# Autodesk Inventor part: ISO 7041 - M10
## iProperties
Comments: To add or edit properties for Autodesk Inventor files, use iProperties.
Created: 2004-03
Part Number: ISO 7041 - M10
Vendor: Autodesk Inc.
Document SubType Name: Modeling
Designer: rak
Material: Default
Description: Hex Nut with Torque Part
Standard: ISO 7041
Size Designation: M10
Alert: To add or edit properties for Autodesk Inventor files, use iProperties.
Control State: 0
Master: False
Checked Out: False
Shininess: 64.0
Length Units: 11269
Angle Units: 11279
Time Units: 11290
Mass Units: 11283
Length Display Precision: 3
Angle Display Precision: 2
Compacted: True
EGR: 1
Density: 0.0
Volumn: 0.0
Area: 0.0
PropertySet Name: Model Information
Author: rak
Revision Number: 8
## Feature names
1. Body [Extrusion]
2. Ring [Extrusion]
3. Chamfer1 [Revolution]
4. Thread [Hole]
5. Chamfer2
6. Chamfer3
